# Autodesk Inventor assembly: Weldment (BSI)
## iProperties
Length Units: 11269
Angle Units: 11283
Time Units: 11279
Mass Units: 11290
Length Display Precision: 3
Angle Display Precision: 2
Part Number: Weldment (BSI)
Document SubType Name: Weldment
Created: 2002-06
Designer: smithga
Created: 2002-08
Control State: 0
Master: False
Shininess: 64.0
Angle Units: 11279
Time Units: 11290
Mass Units: 11283
Compacted: True
Density: 0.0
Volumn: 0.0
Area: 0.0
PropertySet Name: Model Information
